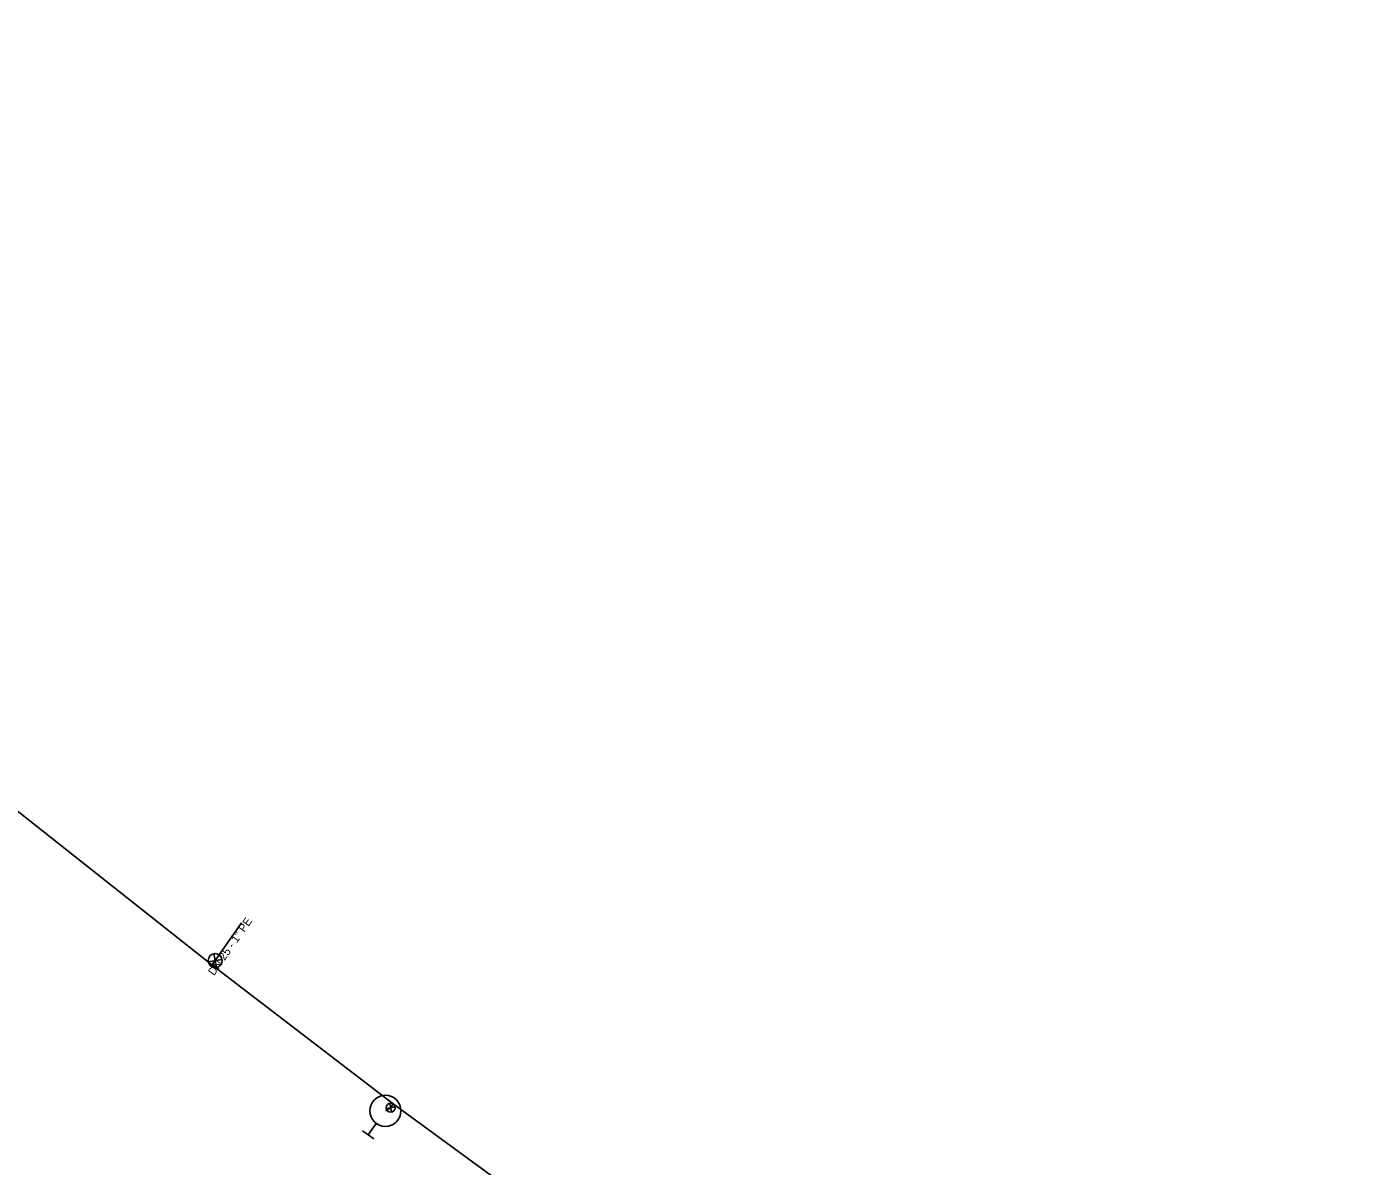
# Model space of a CAD drawing. Extents: x -443519 to -443021, y -1121477 to -1120870.
# Drawn here: x -443331.7 to -443256.5, y -1121243 to -1121178.2 of the extents above; entities that cross this region are included whole.
import ezdxf

# ---------------------------------------------------------------- set-up
doc = ezdxf.new("R2010")
doc.units = 0
for name, color, linetype in [('_hydrantova_odbocka_', 7, 'Continuous'), ('_pripojka_priblizne_', 7, 'Continuous'), ('_voda_smvak_prevzato_z_dokumentace_', 7, 'Continuous'), ('Default', 7, 'Continuous'), ('MoLevel 27', 7, 'Continuous'), ('MoLevel 28', 7, 'Continuous'), ('MoLevel 32', 7, 'Continuous'), ('MoLevel 53', 7, 'Continuous')]:
    doc.layers.add(name, color=color, linetype=linetype)

# ---------------------------------------------------------------- blocks, each defined once
blk = doc.blocks.new('_uzaver_')
at = {"layer": 'Default'}
for p, q in [((-0.000035, -0.000035), (0.000035, 0.000035)), ((0.000035, -0.000035), (-0.000035, 0.000035))]:
    blk.add_line(p, q, dxfattribs=at)
for radius in [0.00005, 0.0000025]:
    blk.add_circle((0, 0), radius, dxfattribs=at)
blk = doc.blocks.new('_uzaver_pripojka_')
at = {"layer": 'Default'}
for p, q in [((-0.000035, -0.000035), (0.000035, 0.000035)), ((0.000035, -0.000035), (-0.000035, 0.000035))]:
    blk.add_line(p, q, dxfattribs=at)
for radius in [0.00005, 0.0000025]:
    blk.add_circle((0, 0), radius, dxfattribs=at)
blk = doc.blocks.new('_hydrant_voda_')
at = {"layer": 'Default'}
for p, q in [((-0.0000225, 0.000095), (0.0000225, 0.000095)), ((0, 0.000095), (0, 0.00005))]:
    blk.add_line(p, q, dxfattribs=at)
blk.add_circle((0, 0), 0.00005, dxfattribs=at)

msp = doc.modelspace()

# ---------------------------------------------------------------- linework, layer by layer
at = {"layer": '_hydrantova_odbocka_'}
msp.add_lwpolyline([(-443310.841, -1121239.434), (-443310.99, -1121239.66), (-443311.29, -1121239.84)], dxfattribs=at)
at = {"layer": '_pripojka_priblizne_'}
msp.add_lwpolyline([(-443321.156, -1121231.535), (-443320.97, -1121231.3), (-443319.472, -1121229.153)], dxfattribs=at)
at = {"layer": '_voda_smvak_prevzato_z_dokumentace_'}
for points in [[(-443385.178, -1121141.753), (-443377.04, -1121157.611), (-443362.958, -1121184.213), (-443358.115, -1121192.908), (-443343.804, -1121211.407), (-443339.066, -1121217.376), (-443321.156, -1121231.535), (-443310.841, -1121239.434)], [(-443310.841, -1121239.434), (-443294.198, -1121251.608), (-443268.857, -1121267.596), (-443245.045, -1121283.381), (-443235.625, -1121289.193)]]:
    msp.add_lwpolyline(points, dxfattribs=at)

# ---------------------------------------------------------------- block references
at = {"layer": 'MoLevel 27', "xscale": 4999.999999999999, "yscale": 5000, "rotation": 56.575188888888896}
msp.add_blockref('_uzaver_', (-443310.99, -1121239.66), dxfattribs=at)
at = {"layer": 'MoLevel 28', "xscale": 17636.68430335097, "yscale": 17636.68430335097, "rotation": 144.240272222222}
msp.add_blockref('_hydrant_voda_', (-443311.29, -1121239.84), dxfattribs=at)
at = {"layer": 'MoLevel 53', "xscale": 8000, "yscale": 7999.999999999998, "rotation": 54.987410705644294}
msp.add_blockref('_uzaver_pripojka_', (-443320.97, -1121231.3), dxfattribs=at)

# ---------------------------------------------------------------- texts
at = {"layer": 'MoLevel 32'}
msp.add_text("DN 25 - 1'' PE", height=0.455, rotation=55.08775, dxfattribs=at).set_placement((-443321.033, -1121232.186))

doc.saveas('drawing.dxf')
